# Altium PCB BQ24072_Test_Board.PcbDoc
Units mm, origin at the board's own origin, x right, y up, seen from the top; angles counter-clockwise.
Board outline 34.29 x 22.86 mm, 2 copper layers (Top Layer, Bottom Layer); 19 components, 13 nets, 63 pads, 17 vias.
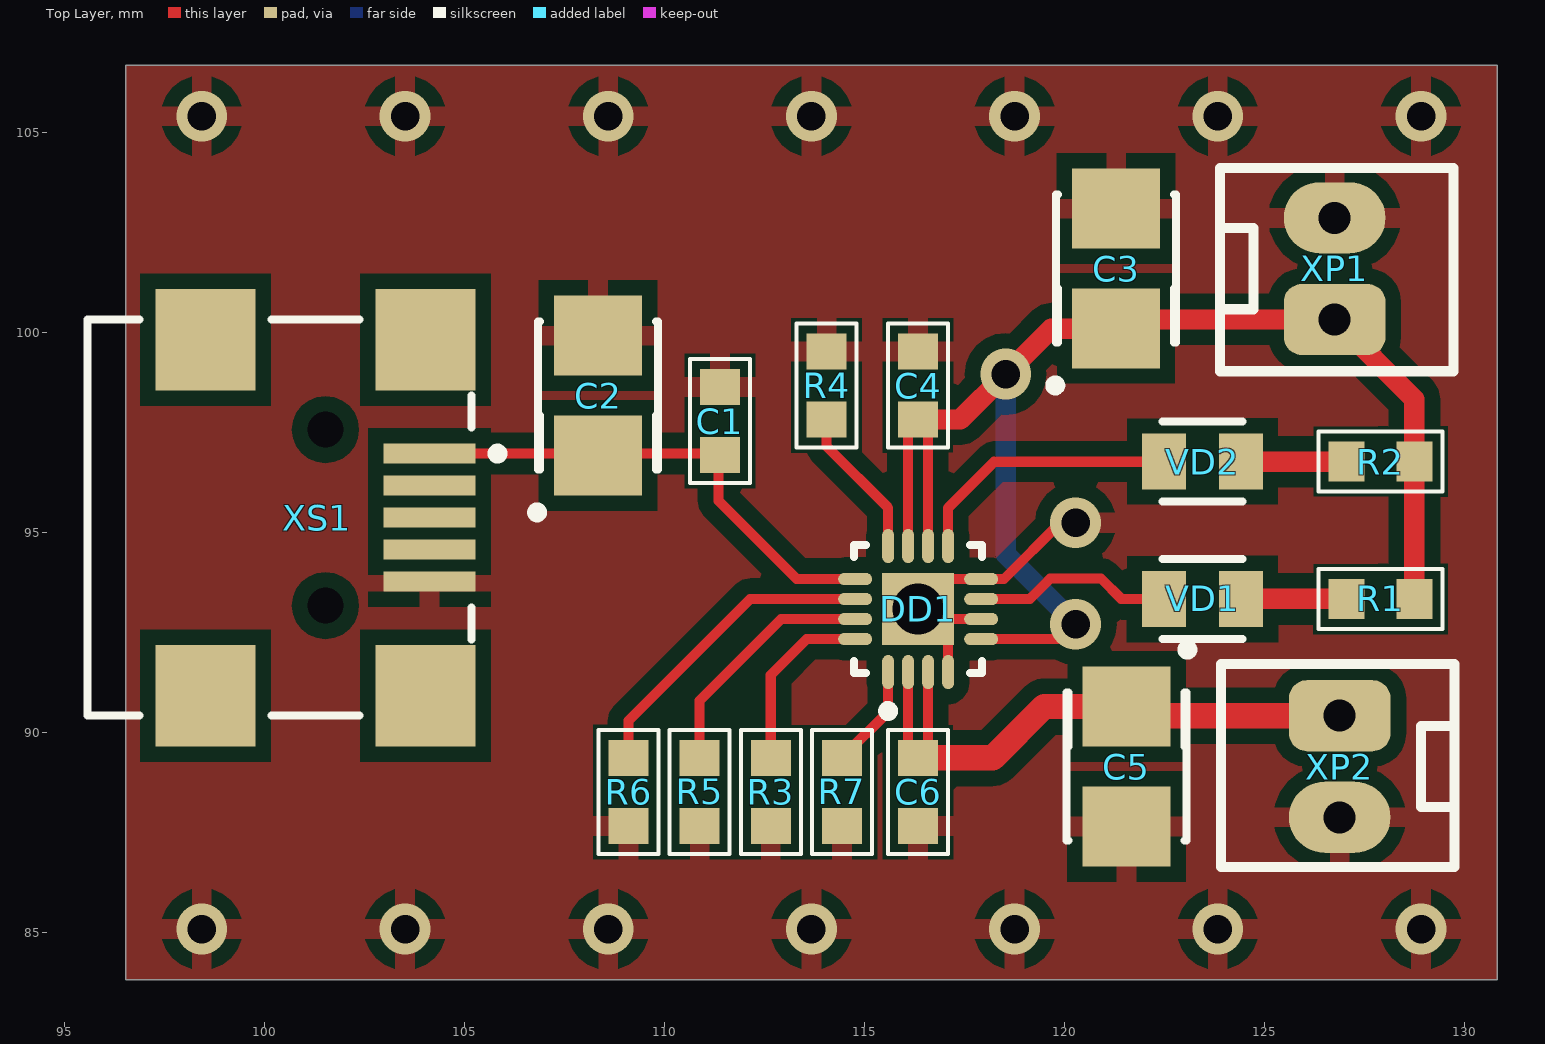
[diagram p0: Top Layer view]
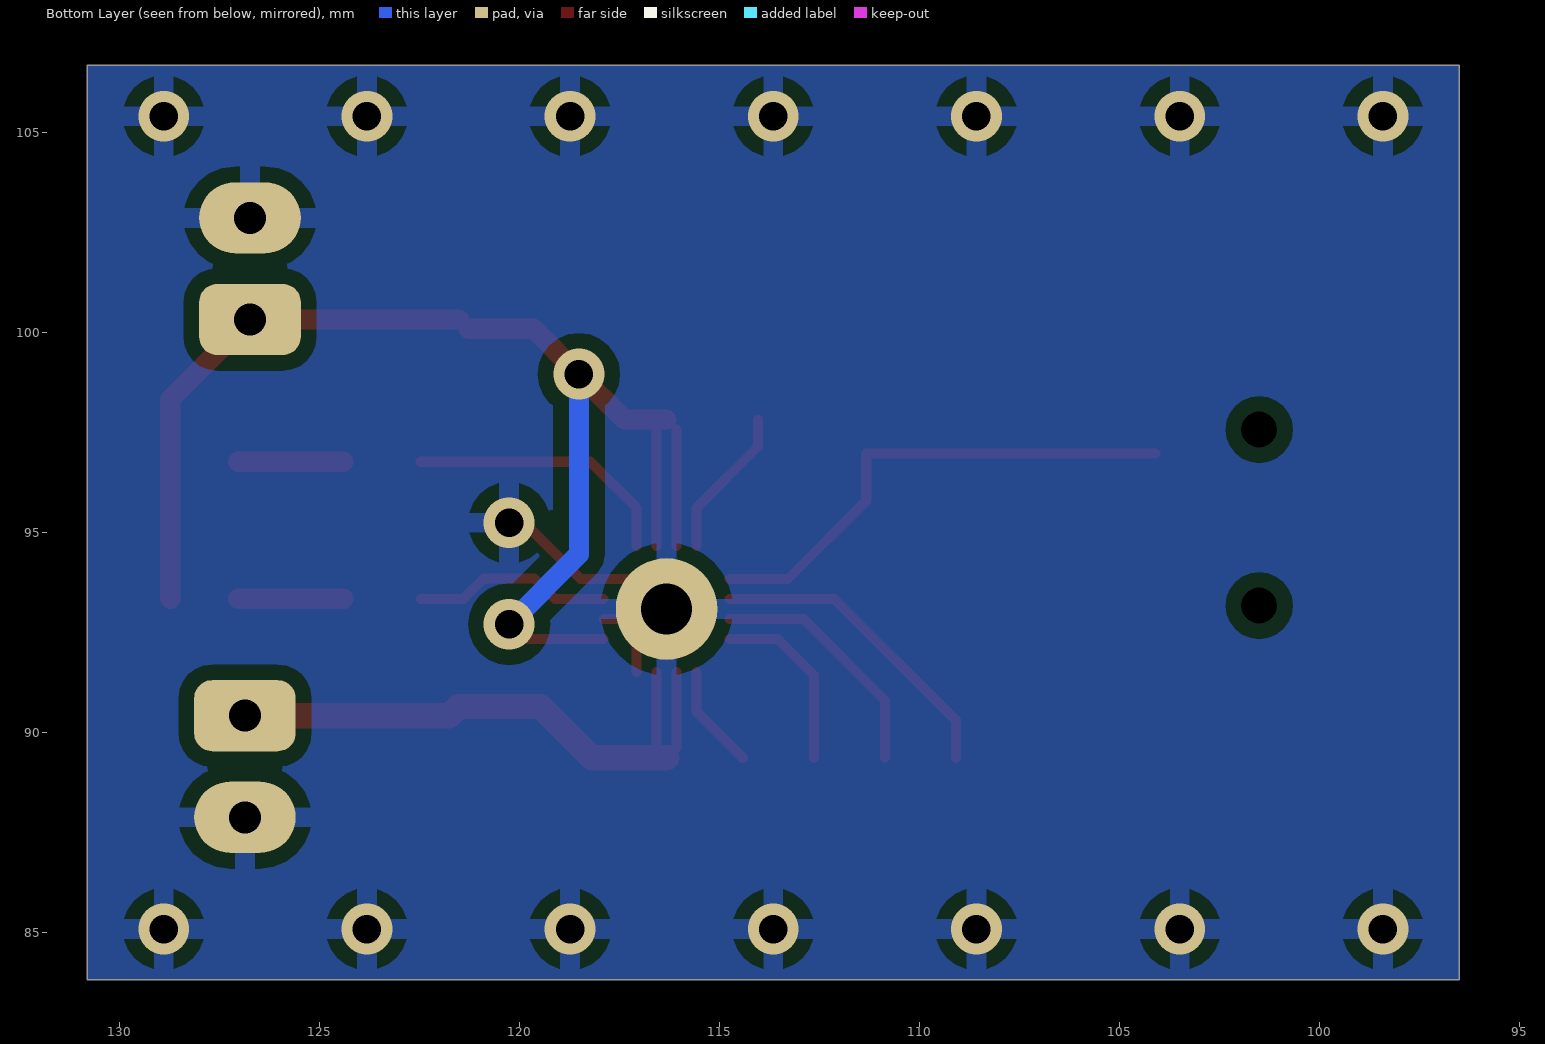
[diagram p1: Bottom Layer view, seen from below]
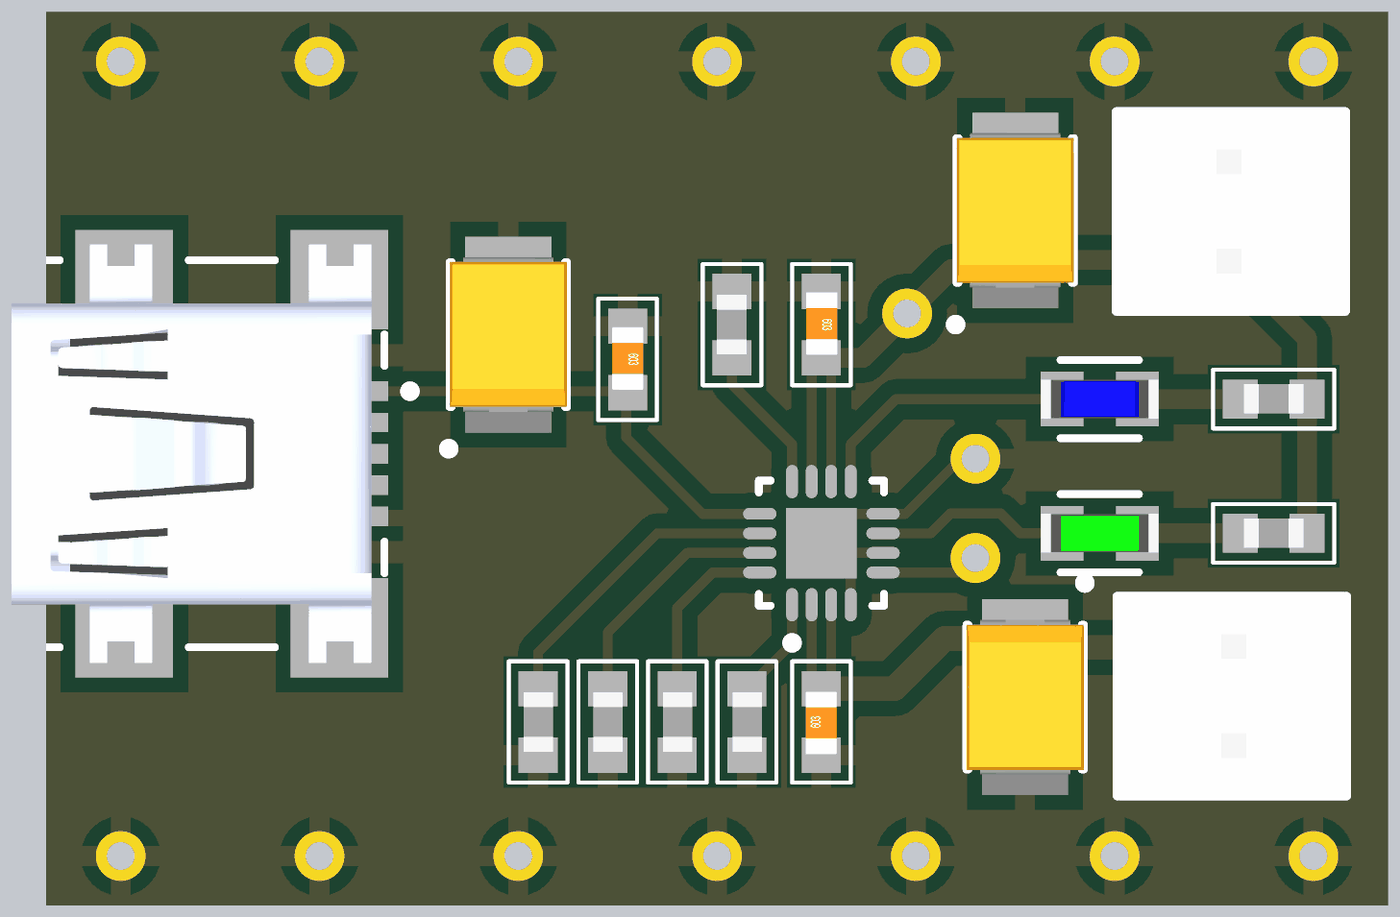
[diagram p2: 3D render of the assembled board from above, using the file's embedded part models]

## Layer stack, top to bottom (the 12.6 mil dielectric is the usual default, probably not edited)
Top Layer: signal copper 0.0356
Dielectric: dielectric 0.32, FR-4, Dk 4.8
Bottom Layer: signal copper 0.0356

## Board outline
96.52,106.68 130.81,106.68 130.81,83.82 96.52,83.82

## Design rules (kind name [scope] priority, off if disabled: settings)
Clearance [All] p1: gap=0.2
PlaneConnect [All] p1: planeconnectstyle=Relief reliefexpansion=0.508 reliefentries=4 reliefconductorwidth=0.508 reliefairgap=0.508
PolygonConnect [All] p1: connectstyle=Relief reliefconductorwidth=0.508 reliefentries=4 polygonreliefangle="90 Angle"
RoutingVias [All] p1: holewidth=0.6 width=1.2 viastyle="Through Hole" minholewidth=0.5 minwidth=1 maxholewidth=0.7 maxwidth=1.4
SilkscreenOverComponentPads [All] p1: minsilkscreentomaskgap=0.254
SolderMaskExpansion [All] p1: expansion=0
Width [All] p1: maxlimit=2.54 minlimit=0.254 preferedwidth=0.254
26 further rules are at their usual default settings.

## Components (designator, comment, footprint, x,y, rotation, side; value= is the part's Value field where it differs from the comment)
C1 "C <0603> 0,1 мкФ±20% 25В" 0603 111.379,97.79 r270 top
C2 "B45197A3106" B-3528-31 108.331,98.425 r90 top
C3 "B45197A3106" B-3528-31 121.285,101.6 r90 top
C4 "C <0603> 0,1 мкФ±20% 25В" 0603 116.332,98.679 r270 top
C5 "B45197A3106" B-3528-31 121.539,89.154 r270 top
C6 "C <0603> 0,1 мкФ±20% 25В" 0603 116.332,88.519 r90 top
DD1 "BQ24072RGT" "QFN-16 (MO-220VEED-4)" 116.332,93.091 r90 top
R1 "R0603-820 Ом-5%" 0603 127.889,93.345 r180 top
R2 "R0603-820 Ом-5%" 0603 127.889,96.774 r180 top
R3 "R0603-3кОм-5%" 0603 112.649,88.519 r90 top
R4 "R0603-1,1кОм-5%" 0603 114.046,98.679 r270 top
R5 "R0603-1 Ом-5%" 0603 110.871,88.519 r90 top
R6 "R0603-1 Ом-5%" 0603 109.093,88.519 r90 top
R7 "R0603-10кОм-5%" 0603 114.427,88.519 r90 top
VD1 "0805_LED_GREEN" 0805_LED_GREEN 123.444,93.345 r180 top
VD2 "0805_LED_BLUE" 0805_LED_BLUE 123.444,96.774 r180 top
XP1 "WF-2" WF-2 126.746,100.33 r90 top
XP2 "WF-2" WF-2 126.873,90.424 r270 top
XS1 "USB/M-1J" USB/M-1J 96.266,95.377 r180 top

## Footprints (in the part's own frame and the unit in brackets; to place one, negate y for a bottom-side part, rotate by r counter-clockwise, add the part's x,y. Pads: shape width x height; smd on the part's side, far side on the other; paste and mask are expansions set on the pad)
0603 [mm]
  rect 0.9x1 smd: 1(-0.85,0) 2(0.85,0)
  silkscreen extent -1.55,-0.75 1.55,0.75, body extent -0.83,-0.39 0.77,0.41, height 0.3
0805_LED_BLUE [mm] "Светодиод SMD типоразмер 0805"
  rect 1.098x1.4 smd: 1(-0.965,0) 2(0.965,0)
  silkscreen extent -1,-1 1,1, body extent -1.5,-0.5 1.5,0.5, height 2
0805_LED_GREEN [mm] "Светодиод SMD типоразмер 0805"
  rect 1.098x1.4 smd: 1(-0.965,0) 2(0.965,0)
  silkscreen extent -1,-1 1,1, body extent -1.5,-0.5 1.5,0.5, height 2
B-3528-31 [mm] "Capacitor, SM Tantalum; Body 3.5 x 2.8 mm (LxW typ)"
  rect 2x2.2 smd: 1(-1.5,0) 2(1.5,0)
  silkscreen extent -3.04,-1.5 1.85,1.65, body extent -2.5,-1.5 2.5,1.5, height 2.11
"QFN-16 (MO-220VEED-4)" [mm] "QFN, 16-Leads, Body 3x3mm, Pitch 0.5mm, IPC Low Density"
  oval 0.85x0.3 smd: 1(-1.575,0.75) 2(-1.575,0.25) 3(-1.575,-0.25) 4(-1.575,-0.75) 9(1.575,-0.75) 10(1.575,-0.25) 11(1.575,0.25) 12(1.575,0.75)
  oval 0.3x0.85 smd: 5(-0.75,-1.575) 6(-0.25,-1.575) 7(0.25,-1.575) 8(0.75,-1.575) 13(0.75,1.575) 14(0.25,1.575) 15(-0.25,1.575) 16(-0.75,1.575)
  rect 1.8x1.8 smd: 17(0,0)
  silkscreen extent -2.67,-1.6 1.6,1.6
USB/M-1J [mm] "Connector; USB2.0, Type B, SM; 5 Position; Right Angle"
  rect 2.3x0.5 smd: 1(-7.85,-1.6) 2(-7.85,-0.8) 3(-7.85,0) 4(-7.85,0.8) 5(-7.85,1.6)
  rect 2.5x2.54 smd: 6(-7.75,-4.45) 6(-7.75,4.45) 6(-2.25,4.45) 6(-2.25,-4.45)
  round 0.6 hole 0.9 unplated: MH1(-5.25,2.2) MH2(-5.25,-2.2)
  silkscreen extent -9.68,-4.95 0.7,4.95, body extent -8.57,-5.35 0.64,5.35, height 3.95
WF-2 [mm] "Разъем питания 2 конт.(п) шаг 2,54 на плату"
  rrect50% 1.778x2.54 hole 0.8: 1(0,0)
  oval 1.778x2.54 hole 0.8: 2(2.54,0)
  silkscreen extent -1.3,-2.97 3.78,2.87, body extent -1.3,-2.97 3.78,2.87, height 11.87

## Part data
C2 C3 C5: "Tantalum Chip Capacitors; Low ESR"
DD1: "1.5A USB-FriendlyLi-Ion battery charger and Power-Path management IC"
VD1 VD2: "Светодиод SMD типоразмер 0805"
XP1 XP2: "Разъем питания 2 конт.(п) шаг 2,54 на плату"
XS1: "Разъем miniUSB (м) на плату, 5 контактов, поверхност. монтаж"

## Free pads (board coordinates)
  round 1.27 / inner round 1.27 / far side round 2.54 hole 1.27: 0(116.332,93.091)

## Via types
v1: diameter 1.27, hole 0.711, Top Layer to Bottom Layer, 17 vias

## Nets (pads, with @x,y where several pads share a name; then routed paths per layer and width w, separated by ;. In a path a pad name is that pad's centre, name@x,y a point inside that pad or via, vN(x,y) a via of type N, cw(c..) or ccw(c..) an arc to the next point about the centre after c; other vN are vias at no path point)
GND: C1.1 C2.2 C3.2 C4.1 C5.2 C6.1 DD1.4 DD1.6 DD1.8 DD1.17 pad.0 R3.1 R4.1 R5.1 R6.1 R7.1 XP1.2 XP2.2 XS1.5 | length 5.9
  Top Layer w0.254: DD1.17@116.582,92.841 DD1.6 ; DD1.4 DD1.17@117.082,92.341 ; DD1.17@117.082,93.841 DD1.8 118.479,93.841 119.888,95.25 v1(120.269,95.25)
  other v1: 98.425,85.09 103.505,85.09 108.585,85.09 113.665,85.09 118.745,85.09 123.825,85.09 128.905,85.09 98.425,105.41 103.505,105.41 108.585,105.41 113.665,105.41 118.745,105.41 123.825,105.41 128.905,105.41
NetC1_2: C1.2 C2.1 DD1.13 XS1.1 | length 12.6
  Top Layer w0.254: XS1.1 111.342,96.977 111.342,95.795 113.296,93.841 DD1.13
NetC3_1: C3.1 C4.2 DD1.5 DD1.10 DD1.11 R1.1 R2.1 XP1.1 | length 33.7
  Top Layer w0.254: DD1.11 C4.2@116.082,97.579 ; DD1.10 C4.2@116.582,97.579 ; DD1.5 v1@119.9,92.341
  Top Layer w0.508: C4.2 117.387,97.829 v1(118.523,98.965) 119.658,100.1 C3.1 ; C3.1@121.515,100.33 XP1.1 128.739,98.337 R2.1 R1.1
  Bottom Layer w0.508: v1(118.523,98.965) 118.523,94.456 v1(120.269,92.71)
NetC5_1: C5.1 C6.2 DD1.2 DD1.3 XP2.1 | length 15
  Top Layer w0.254: C6.2@116.082,89.619 DD1.2 ; C6.2@116.582,89.619 DD1.3
  Top Layer w0.635: C6.2 118.198,89.369 119.483,90.654 C5.1 121.769,90.424 XP2.1
NetDD1_1: DD1.1 R7.2 | length 2.6
  Top Layer w0.254: R7.2 115.582,90.524 DD1.1
NetDD1_7: DD1.7 VD1.2 | length 5
  Top Layer w0.254: DD1.7 119.122,93.341 119.634,93.853 120.904,93.853 121.412,93.345 VD1.2
NetDD1_9: DD1.9 VD2.2 | length 6.8
  Top Layer w0.254: DD1.9 117.082,95.619 118.237,96.774 VD2.2
NetDD1_12: DD1.12 R4.2 | length 3.8
  Top Layer w0.254: R4.2 114.046,97.155 115.582,95.619 DD1.12
NetDD1_14: DD1.14 R6.2 | length 7.9
  Top Layer w0.254: R6.2 109.093,90.297 112.137,93.341 DD1.14
NetDD1_15: DD1.15 R5.2 | length 6.2
  Top Layer w0.254: R5.2 110.871,90.805 112.907,92.841 DD1.15
NetDD1_16: DD1.16 R3.2 | length 4.6
  Top Layer w0.254: R3.2 112.649,91.44 113.55,92.341 DD1.16
NetR1_2: R1.2 VD1.1 | length 2.6
  Top Layer w0.508: VD1.1 R1.2
NetR2_2: R2.2 VD2.1 | length 2.6
  Top Layer w0.508: VD2.1 R2.2
pads on no net: XS1.2 XS1.3 XS1.4 XS1.6 XS1.MH1 XS1.MH2

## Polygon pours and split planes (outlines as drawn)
GND on Bottom Layer "BottomPolygon" (solid, pour order 4): 96.52,106.68 130.81,106.68 130.81,83.82 96.52,83.82
GND on Top Layer "TopPolygon" (solid, pour order 8): 96.52,83.82 130.81,83.82 130.81,106.68 96.52,106.68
